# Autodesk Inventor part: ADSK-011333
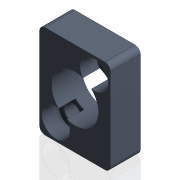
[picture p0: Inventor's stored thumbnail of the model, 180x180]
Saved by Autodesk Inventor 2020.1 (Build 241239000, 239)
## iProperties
Created: 1999-12
Part Number: ADSK-011333
Material: Pearson Nylatron
Description: 10,015,020,NUT,FLOATING,0.750-06RH
Document SubType Name: Modeling
Designer: sspink
Density: 1.13867 g/cm^3
Appearance: Nylatron
Mass: 24.1151 g
Surface Area: 78.8473 cm^2
Volume: 21.1783 cm^3
Control State: 0
Checked Out: False
Master: False
Shininess: 10.0
Length Units: 11269
Angle Units: 11279
Time Units: 11290
Mass Units: 11283
Length Display Precision: 3
Angle Display Precision: 2
Compacted: True
Dimensions: 38x50x16 mm
Mass: 0,024 kg
DocNumber: ADSK-011333.ipt
Folder: 01 - Themengebiete\Simplification\01 - Packaging machine\
VDS_Category: 3D Komponenten
Density: 1.13867
Volumn: 24.253313237459647
Area: 77.26566677878486
PropertySet Name: Model Information
Author: sspink
Revision Number: -
Title: 10,015,020,NUT,FLOATING,0.750-06RH
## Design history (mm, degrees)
node "Solide1"
  node "Extrusion1" dims "d2" = 16, "d3" = 0
  node "Hole1" dims "d8" = 9, "d9" = 15, "d10" = 9, "d11" = 60 deg, "d12" = 19.05, "d13" = 118 deg, "d29" = 6
  node "Hole2" dims "d14" = 20, "d15" = 9.525, "d16" = 6.35, "d17" = 60 deg, "d18" = 19.05, "d19" = 118 deg, "d26" = 12.7
  node "Fillet1" dims "d20" = 3
sketch "Sketch1"
  geometry: L1 (19, -25)-(-19, -25); L2 (-19, -25)-(-19, 25); L3 (-19, 25)-(19, 25); L4 (19, 25)-(19, -25); 3 further points
  constraints: 8 end point, 2 midpoint, 2 parallel, 1 horizontal, 1 horizontal alignment, 1 perpendicular, 1 vertical alignment
  dimensions: "d0" = 50 distance of L3.end L1.start; "d1" = 38 distance of L1.start L1.end
sketch "Sketch2"
  geometry: L1 (-19, 25)-(19, 25) reference; L2 (-19, -25)-(-19, 25) reference; L3 (-10.25, -16.25)-(10.25, -16.25); L4 (10.25, -16.25)-(10.25, 16.25); L5 (10.25, 16.25)-(-10.25, 16.25); L6 (-10.25, 16.25)-(-10.25, -16.25); 4 further points
  constraints: 8 end point, 4 midpoint, 2 parallel, 1 horizontal, 1 horizontal alignment, 1 perpendicular, 1 vertical alignment
  dimensions: "d27" = 32.5 distance of L5.end L3.start; "d28" = 20.5 distance of L4.end L5.end
sketch "Sketch3"
  geometry: 2 further points
  constraints: 1 coincident
node "Corps solides"
node "Corps surfaciques"
